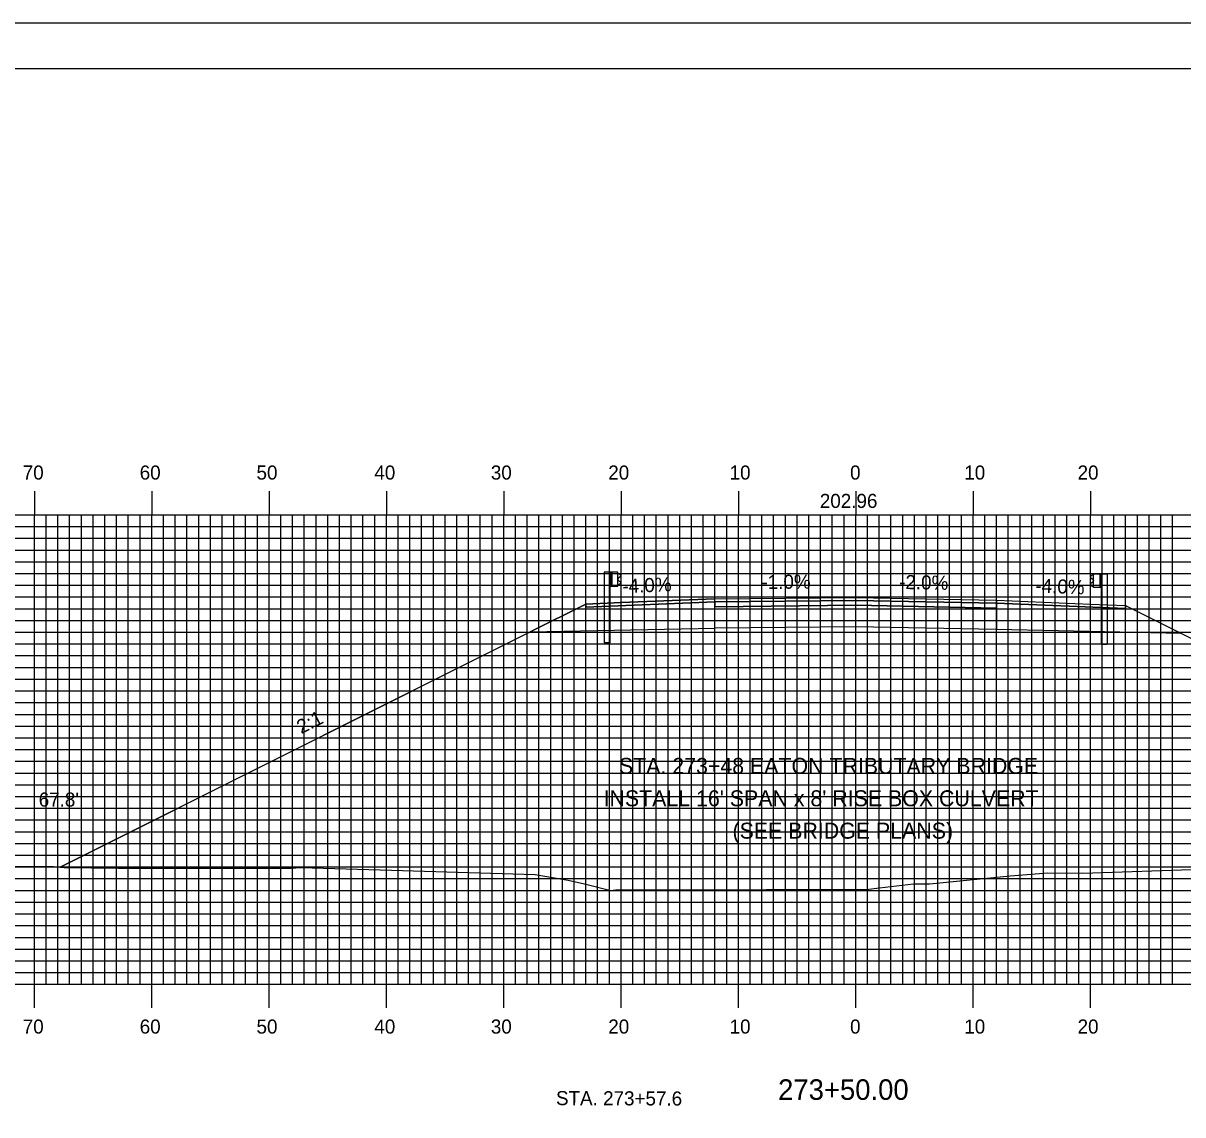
# Model space of a CAD drawing. Extents: x 1809013 to 1809356, y 442591 to 442811.
# Drawn here: x 1809107.4 to 1809206.2, y 442717.5 to 442810.5 of the extents above; entities that cross this region are included whole.
import ezdxf

# ---------------------------------------------------------------- set-up
doc = ezdxf.new("R2010")
doc.units = 0
for name, color, linetype in [('ANNOTATION', 7, 'Continuous'), ('BORDER', 7, 'Continuous'), ('BORING - NO REFUSAL', 7, 'Continuous'), ('D_Guardrail_Beam_Lt', 7, 'Continuous'), ('D_Guardrail_Beam_Rt', 7, 'Continuous'), ('D_Roadway_Centerline', 7, 'Continuous'), ('D_Roadway_Centerline_Text', 7, 'Continuous'), ('D_Roadway_Edge_Shoulder', 7, 'Continuous'), ('D_Roadway_Edge_TW', 7, 'Continuous'), ('D_Roadway_Pavement', 7, 'Continuous'), ('D_Roadway_SlopeLines', 7, 'Continuous'), ('D_Roadway_SubGrade', 7, 'Continuous'), ('D_Text_Standard', 7, 'Continuous'), ('H_V ANNOTATION', 7, 'Continuous'), ('MAJOR', 7, 'Continuous'), ('MINOR', 7, 'Continuous'), ('PLOT BOUNDARY', 7, 'Continuous'), ('S_Roadway_Centerline', 7, 'Continuous')]:
    doc.layers.add(name, color=color, linetype=linetype)

msp = doc.modelspace()

# ---------------------------------------------------------------- linework, layer by layer
at = {"layer": 'BORDER'}
msp.add_lwpolyline([(1809028.724, 442596.665), (1809348.724, 442596.665), (1809348.724, 442806.665), (1809028.724, 442806.665)], close=True, dxfattribs=at)
at = {"layer": 'D_Guardrail_Beam_Lt'}
for p, q in [((1809156.895, 442763.763), (1809156.895, 442757.763)), ((1809157.366, 442763.763), (1809156.895, 442763.763)), ((1809158.053, 442763.763), (1809157.366, 442763.763)), ((1809157.366, 442763.763), (1809157.366, 442762.596)), ((1809157.428, 442763.763), (1809157.428, 442762.596)), ((1809157.533, 442763.763), (1809157.533, 442762.596)), ((1809158.053, 442762.596), (1809158.053, 442763.763)), ((1809158.053, 442763.679), (1809158.128, 442763.665)), ((1809158.143, 442763.658), (1809158.287, 442763.558)), ((1809157.366, 442762.596), (1809158.053, 442762.596)), ((1809157.387, 442757.763), (1809157.387, 442762.596)), ((1809158.128, 442762.694), (1809158.053, 442762.679)), ((1809158.058, 442763.214), (1809158.058, 442763.144)), ((1809158.287, 442763.415), (1809158.091, 442763.279)), ((1809158.091, 442763.08), (1809158.287, 442762.944)), ((1809158.287, 442762.801), (1809158.143, 442762.701)), ((1809157.387, 442757.763), (1809156.895, 442757.763))]:
    msp.add_line(p, q, dxfattribs=at)
for centre, major_axis, start_param, end_param in [((1809158.119, 442763.624), (0.0417, 0), 0.959931, 1.376053), ((1809158.236, 442763.486), (0.0877, 0), 5.323254, 7.243116), ((1809158.137, 442763.214), (-0.0789, 0), 5.323254, 6.283185), ((1809158.137, 442763.144), (-0.0789, 0), 6.283185, 7.243116), ((1809158.119, 442762.735), (0.0417, 0), 4.907132, 5.323254), ((1809158.236, 442762.872), (0.0877, 0), 5.323254, 7.243116)]:
    msp.add_ellipse(centre, major_axis=major_axis, ratio=0.995501, start_param=start_param, end_param=end_param, dxfattribs=at)
at = {"layer": 'D_Guardrail_Beam_Rt'}
for p, q in [((1809198.505, 442763.539), (1809198.362, 442763.439)), ((1809198.595, 442763.56), (1809198.521, 442763.546)), ((1809198.595, 442763.644), (1809199.283, 442763.644)), ((1809198.595, 442762.477), (1809198.595, 442763.644)), ((1809199.116, 442763.644), (1809199.116, 442762.477)), ((1809199.22, 442763.644), (1809199.22, 442762.477)), ((1809199.283, 442763.644), (1809199.753, 442763.644)), ((1809199.283, 442763.644), (1809199.283, 442762.477)), ((1809199.753, 442763.644), (1809199.753, 442757.644)), ((1809198.362, 442763.296), (1809198.557, 442763.16)), ((1809198.557, 442762.961), (1809198.362, 442762.825)), ((1809198.362, 442762.681), (1809198.505, 442762.581)), ((1809198.521, 442762.575), (1809198.595, 442762.56)), ((1809198.591, 442763.095), (1809198.591, 442763.025)), ((1809199.283, 442762.477), (1809198.595, 442762.477)), ((1809199.262, 442757.644), (1809199.262, 442762.477)), ((1809199.262, 442757.644), (1809199.753, 442757.644))]:
    msp.add_line(p, q, dxfattribs=at)
for centre, major_axis, start_param, end_param in [((1809198.529, 442763.505), (-0.0417, 0), 4.907132, 5.323254), ((1809198.412, 442763.367), (-0.0877, 0), 5.323254, 7.243116), ((1809198.412, 442762.753), (-0.0877, 0), 5.323254, 7.243116), ((1809198.529, 442762.615), (-0.0417, 0), 0.959931, 1.376053), ((1809198.512, 442763.095), (0.0789, 0), 0, 0.959931), ((1809198.512, 442763.025), (0.0789, 0), 5.323254, 6.283185)]:
    msp.add_ellipse(centre, major_axis=major_axis, ratio=0.995501, start_param=start_param, end_param=end_param, dxfattribs=at)
at = {"layer": 'D_Roadway_Centerline'}
msp.add_lwpolyline([(1809110.506, 442738.65), (1809150.574, 442758.684), (1809155.324, 442761.059), (1809158.324, 442761.179), (1809166.324, 442761.499), (1809178.324, 442761.62), (1809190.324, 442761.38), (1809198.324, 442761.06), (1809201.324, 442760.94), (1809206.074, 442758.565), (1809246.409, 442738.398)], dxfattribs=at)
at = {"layer": 'D_Roadway_Edge_Shoulder'}
for points in [[(1809166.324, 442761.499), (1809158.324, 442761.179), (1809158.324, 442761.179), (1809155.324, 442761.059), (1809155.324, 442760.809), (1809166.324, 442761.249)], [(1809190.324, 442761.38), (1809198.324, 442761.06), (1809198.324, 442761.06), (1809201.324, 442760.94), (1809201.324, 442760.69), (1809190.324, 442761.13)]]:
    msp.add_lwpolyline(points, close=True, dxfattribs=at)
at = {"layer": 'D_Roadway_Edge_TW'}
msp.add_lwpolyline([(1809166.324, 442761.249), (1809166.324, 442761.499), (1809178.324, 442761.62), (1809190.324, 442761.38), (1809190.324, 442761.13), (1809178.324, 442761.37)], close=True, dxfattribs=at)
at = {"layer": 'D_Roadway_Pavement'}
msp.add_lwpolyline([(1809166.324, 442760.833), (1809166.324, 442761.249), (1809178.324, 442761.37), (1809190.324, 442761.13), (1809190.324, 442760.714), (1809178.324, 442760.954)], close=True, dxfattribs=at)
for points in [[(1809166.324, 442761.249), (1809166.324, 442760.833)], [(1809190.324, 442761.13), (1809190.324, 442760.714)]]:
    msp.add_lwpolyline(points, dxfattribs=at)
at = {"layer": 'D_Roadway_SlopeLines'}
for points in [[(1809155.324, 442761.059), (1809110.506, 442738.65)], [(1809201.324, 442760.94), (1809246.409, 442738.398)]]:
    msp.add_lwpolyline(points, dxfattribs=at)
at = {"layer": 'D_Roadway_SubGrade'}
for points in [[(1809166.324, 442760.833), (1809166.324, 442761.249), (1809155.324, 442760.809), (1809155.324, 442761.059), (1809150.574, 442758.684), (1809166.324, 442758.999)], [(1809166.324, 442758.999), (1809166.324, 442761.249), (1809166.324, 442760.833), (1809178.324, 442760.954), (1809190.324, 442760.714), (1809190.324, 442761.13), (1809190.324, 442758.88), (1809178.324, 442759.12)], [(1809190.324, 442760.714), (1809190.324, 442761.13), (1809201.324, 442760.69), (1809201.324, 442760.94), (1809206.074, 442758.565), (1809190.324, 442758.88)]]:
    msp.add_lwpolyline(points, close=True, dxfattribs=at)
at = {"layer": 'MAJOR'}
for p, q in [((1809108.324, 442770.669), (1809108.324, 442768.665)), ((1809118.324, 442770.669), (1809118.324, 442768.665)), ((1809128.324, 442770.669), (1809128.324, 442768.665)), ((1809138.324, 442770.669), (1809138.324, 442768.665)), ((1809148.324, 442770.669), (1809148.324, 442768.665)), ((1809158.324, 442770.669), (1809158.324, 442768.665)), ((1809168.324, 442770.669), (1809168.324, 442768.665)), ((1809178.324, 442770.669), (1809178.324, 442768.665)), ((1809188.324, 442770.669), (1809188.324, 442768.665)), ((1809198.324, 442770.669), (1809198.324, 442768.665)), ((1809038.324, 442768.665), (1809318.324, 442768.665)), ((1809038.324, 442768.665), (1809318.324, 442768.665)), ((1809108.324, 442728.665), (1809108.324, 442768.665)), ((1809118.324, 442728.665), (1809118.324, 442768.665)), ((1809128.324, 442728.665), (1809128.324, 442768.665)), ((1809138.324, 442728.665), (1809138.324, 442768.665)), ((1809148.324, 442728.665), (1809148.324, 442768.665)), ((1809158.324, 442728.665), (1809158.324, 442768.665)), ((1809168.324, 442728.665), (1809168.324, 442768.665)), ((1809178.324, 442728.665), (1809178.324, 442768.665)), ((1809188.324, 442728.665), (1809188.324, 442768.665)), ((1809198.324, 442728.665), (1809198.324, 442768.665)), ((1809038.324, 442763.665), (1809318.324, 442763.665)), ((1809038.324, 442758.665), (1809318.324, 442758.665)), ((1809038.324, 442753.665), (1809318.324, 442753.665)), ((1809038.324, 442748.665), (1809318.324, 442748.665)), ((1809038.324, 442743.665), (1809318.324, 442743.665)), ((1809038.324, 442738.665), (1809318.324, 442738.665)), ((1809038.324, 442733.665), (1809318.324, 442733.665)), ((1809038.324, 442728.665), (1809318.324, 442728.665)), ((1809038.324, 442728.665), (1809318.324, 442728.665)), ((1809108.324, 442726.661), (1809108.324, 442728.665)), ((1809118.324, 442726.661), (1809118.324, 442728.665)), ((1809128.324, 442726.661), (1809128.324, 442728.665)), ((1809138.324, 442726.661), (1809138.324, 442728.665)), ((1809148.324, 442726.661), (1809148.324, 442728.665)), ((1809158.324, 442726.661), (1809158.324, 442728.665)), ((1809168.324, 442726.661), (1809168.324, 442728.665)), ((1809178.324, 442726.661), (1809178.324, 442728.665)), ((1809188.324, 442726.661), (1809188.324, 442728.665)), ((1809198.324, 442726.661), (1809198.324, 442728.665))]:
    msp.add_line(p, q, dxfattribs=at)
at = {"layer": 'MINOR'}
for p, q in [((1809109.324, 442728.665), (1809109.324, 442768.665)), ((1809110.324, 442728.665), (1809110.324, 442768.665)), ((1809111.324, 442728.665), (1809111.324, 442768.665)), ((1809112.324, 442728.665), (1809112.324, 442768.665)), ((1809113.324, 442728.665), (1809113.324, 442768.665)), ((1809114.324, 442728.665), (1809114.324, 442768.665)), ((1809115.324, 442728.665), (1809115.324, 442768.665)), ((1809116.324, 442728.665), (1809116.324, 442768.665)), ((1809117.324, 442728.665), (1809117.324, 442768.665)), ((1809119.324, 442728.665), (1809119.324, 442768.665)), ((1809120.324, 442728.665), (1809120.324, 442768.665)), ((1809121.324, 442728.665), (1809121.324, 442768.665)), ((1809122.324, 442728.665), (1809122.324, 442768.665)), ((1809123.324, 442728.665), (1809123.324, 442768.665)), ((1809124.324, 442728.665), (1809124.324, 442768.665)), ((1809125.324, 442728.665), (1809125.324, 442768.665)), ((1809126.324, 442728.665), (1809126.324, 442768.665)), ((1809127.324, 442728.665), (1809127.324, 442768.665)), ((1809129.324, 442728.665), (1809129.324, 442768.665)), ((1809130.324, 442728.665), (1809130.324, 442768.665)), ((1809131.324, 442728.665), (1809131.324, 442768.665)), ((1809132.324, 442728.665), (1809132.324, 442768.665)), ((1809133.324, 442728.665), (1809133.324, 442768.665)), ((1809134.324, 442728.665), (1809134.324, 442768.665)), ((1809135.324, 442728.665), (1809135.324, 442768.665)), ((1809136.324, 442728.665), (1809136.324, 442768.665)), ((1809137.324, 442728.665), (1809137.324, 442768.665)), ((1809139.324, 442728.665), (1809139.324, 442768.665)), ((1809140.324, 442728.665), (1809140.324, 442768.665)), ((1809141.324, 442728.665), (1809141.324, 442768.665)), ((1809142.324, 442728.665), (1809142.324, 442768.665)), ((1809143.324, 442728.665), (1809143.324, 442768.665)), ((1809144.324, 442728.665), (1809144.324, 442768.665)), ((1809145.324, 442728.665), (1809145.324, 442768.665)), ((1809146.324, 442728.665), (1809146.324, 442768.665)), ((1809147.324, 442728.665), (1809147.324, 442768.665)), ((1809149.324, 442728.665), (1809149.324, 442768.665)), ((1809150.324, 442728.665), (1809150.324, 442768.665)), ((1809151.324, 442728.665), (1809151.324, 442768.665)), ((1809152.324, 442728.665), (1809152.324, 442768.665)), ((1809153.324, 442728.665), (1809153.324, 442768.665)), ((1809154.324, 442728.665), (1809154.324, 442768.665)), ((1809155.324, 442728.665), (1809155.324, 442768.665)), ((1809156.324, 442728.665), (1809156.324, 442768.665)), ((1809157.324, 442728.665), (1809157.324, 442768.665)), ((1809159.324, 442728.665), (1809159.324, 442768.665)), ((1809160.324, 442728.665), (1809160.324, 442768.665)), ((1809161.324, 442728.665), (1809161.324, 442768.665)), ((1809162.324, 442728.665), (1809162.324, 442768.665)), ((1809163.324, 442728.665), (1809163.324, 442768.665)), ((1809164.324, 442728.665), (1809164.324, 442768.665)), ((1809165.324, 442728.665), (1809165.324, 442768.665)), ((1809166.324, 442728.665), (1809166.324, 442768.665)), ((1809167.324, 442728.665), (1809167.324, 442768.665)), ((1809169.324, 442728.665), (1809169.324, 442768.665)), ((1809170.324, 442728.665), (1809170.324, 442768.665)), ((1809171.324, 442728.665), (1809171.324, 442768.665)), ((1809172.324, 442728.665), (1809172.324, 442768.665)), ((1809173.324, 442728.665), (1809173.324, 442768.665)), ((1809174.324, 442728.665), (1809174.324, 442768.665)), ((1809175.324, 442728.665), (1809175.324, 442768.665)), ((1809176.324, 442728.665), (1809176.324, 442768.665)), ((1809177.324, 442728.665), (1809177.324, 442768.665)), ((1809179.324, 442728.665), (1809179.324, 442768.665)), ((1809180.324, 442728.665), (1809180.324, 442768.665)), ((1809181.324, 442728.665), (1809181.324, 442768.665)), ((1809182.324, 442728.665), (1809182.324, 442768.665)), ((1809183.324, 442728.665), (1809183.324, 442768.665)), ((1809184.324, 442728.665), (1809184.324, 442768.665)), ((1809185.324, 442728.665), (1809185.324, 442768.665)), ((1809186.324, 442728.665), (1809186.324, 442768.665)), ((1809187.324, 442728.665), (1809187.324, 442768.665)), ((1809189.324, 442728.665), (1809189.324, 442768.665)), ((1809190.324, 442728.665), (1809190.324, 442768.665)), ((1809191.324, 442728.665), (1809191.324, 442768.665)), ((1809192.324, 442728.665), (1809192.324, 442768.665)), ((1809193.324, 442728.665), (1809193.324, 442768.665)), ((1809194.324, 442728.665), (1809194.324, 442768.665)), ((1809195.324, 442728.665), (1809195.324, 442768.665)), ((1809196.324, 442728.665), (1809196.324, 442768.665)), ((1809197.324, 442728.665), (1809197.324, 442768.665)), ((1809199.324, 442728.665), (1809199.324, 442768.665)), ((1809200.324, 442728.665), (1809200.324, 442768.665)), ((1809201.324, 442728.665), (1809201.324, 442768.665)), ((1809202.324, 442728.665), (1809202.324, 442768.665)), ((1809203.324, 442728.665), (1809203.324, 442768.665)), ((1809204.324, 442728.665), (1809204.324, 442768.665)), ((1809205.324, 442728.665), (1809205.324, 442768.665)), ((1809038.324, 442767.665), (1809318.324, 442767.665)), ((1809038.324, 442766.665), (1809318.324, 442766.665)), ((1809038.324, 442765.665), (1809318.324, 442765.665)), ((1809038.324, 442764.665), (1809318.324, 442764.665)), ((1809038.324, 442762.665), (1809318.324, 442762.665)), ((1809038.324, 442761.665), (1809318.324, 442761.665)), ((1809038.324, 442760.665), (1809318.324, 442760.665)), ((1809038.324, 442759.665), (1809318.324, 442759.665)), ((1809038.324, 442757.665), (1809318.324, 442757.665)), ((1809038.324, 442756.665), (1809318.324, 442756.665)), ((1809038.324, 442755.665), (1809318.324, 442755.665)), ((1809038.324, 442754.665), (1809318.324, 442754.665)), ((1809038.324, 442752.665), (1809318.324, 442752.665)), ((1809038.324, 442751.665), (1809318.324, 442751.665)), ((1809038.324, 442750.665), (1809318.324, 442750.665)), ((1809038.324, 442749.665), (1809318.324, 442749.665)), ((1809038.324, 442747.665), (1809318.324, 442747.665)), ((1809038.324, 442746.665), (1809318.324, 442746.665)), ((1809038.324, 442745.665), (1809318.324, 442745.665)), ((1809038.324, 442744.665), (1809318.324, 442744.665)), ((1809038.324, 442742.665), (1809318.324, 442742.665)), ((1809038.324, 442741.665), (1809318.324, 442741.665)), ((1809038.324, 442740.665), (1809318.324, 442740.665)), ((1809038.324, 442739.665), (1809318.324, 442739.665)), ((1809038.324, 442737.665), (1809318.324, 442737.665)), ((1809038.324, 442736.665), (1809318.324, 442736.665)), ((1809038.324, 442735.665), (1809318.324, 442735.665)), ((1809038.324, 442734.665), (1809318.324, 442734.665)), ((1809038.324, 442732.665), (1809318.324, 442732.665)), ((1809038.324, 442731.665), (1809318.324, 442731.665)), ((1809038.324, 442730.665), (1809318.324, 442730.665)), ((1809038.324, 442729.665), (1809318.324, 442729.665))]:
    msp.add_line(p, q, dxfattribs=at)
at = {"layer": 'PLOT BOUNDARY'}
msp.add_lwpolyline([(1809012.538, 442590.547), (1809352.538, 442590.547), (1809352.538, 442810.547), (1809012.538, 442810.547)], close=True, dxfattribs=at)
at = {"layer": 'S_Roadway_Centerline'}
msp.add_lwpolyline([(1809083.821, 442739.145), (1809107.986, 442738.706), (1809109.956, 442738.692), (1809110.869, 442738.623), (1809115.487, 442738.557), (1809130.201, 442738.555), (1809131.043, 442738.627), (1809138.768, 442738.398), (1809151.004, 442738.006), (1809153.805, 442737.544), (1809155.195, 442737.232), (1809157.333, 442736.691), (1809157.412, 442736.65), (1809157.869, 442736.716), (1809170.714, 442736.739), (1809179.222, 442736.752), (1809180.357, 442736.883), (1809183.239, 442737.215), (1809184.632, 442737.22), (1809191.496, 442737.908), (1809194.703, 442738.166), (1809197.67, 442738.136), (1809207.771, 442738.478)], dxfattribs=at)

# ---------------------------------------------------------------- texts
at = {"layer": 'ANNOTATION'}
for s, rotation, p in [('-1.0%', 0.57743, (1809170.293, 442762.339)), ('-2.0%', 358.85424, (1809182.01, 442762.347)), ('-4.0%', 2.29061, (1809158.456, 442761.986)), ('-4.0%', 357.70939, (1809193.616, 442762.05)), ('2:1', 26.56505, (1809131.06, 442749.963))]:
    msp.add_text(s, height=1.2, rotation=rotation, dxfattribs=at).set_placement(p)
for s, p in [('STA. 273+48 EATON TRIBUTARY BRIDGE', (1809158.141, 442746.593)), ("INSTALL 16' SPAN x 8' RISE BOX CULVERT", (1809156.831, 442743.833)), ('(SEE BRIDGE PLANS)', (1809167.82, 442741.073))]:
    msp.add_text(s, height=1.36, dxfattribs=at).set_placement(p)
at = {"layer": 'BORING - NO REFUSAL'}
msp.add_text('STA. 273+57.6', height=1.2, rotation=359.81416, dxfattribs=at).set_placement((1809152.776, 442718.37))
at = {"layer": 'D_Roadway_Centerline'}
for s, p in [('C', (1809178.319, 442761.62)), ('L', (1809178.324, 442761.613))]:
    msp.add_text(s, height=0.0146, dxfattribs=at).set_placement(p)
at = {"layer": 'D_Roadway_Centerline_Text'}
msp.add_text('202.96', height=1.2, dxfattribs=at).set_placement((1809175.263, 442769.248))
at = {"layer": 'D_Text_Standard'}
msp.add_text("67.8'", height=1.2, dxfattribs=at).set_placement((1809108.69, 442743.804))
at = {"layer": 'H_V ANNOTATION'}
for s, height, p in [('70', 1.2, (1809107.328, 442771.665)), ('60', 1.2, (1809117.297, 442771.665)), ('50', 1.2, (1809127.254, 442771.665)), ('40', 1.2, (1809137.297, 442771.665)), ('30', 1.2, (1809147.222, 442771.665)), ('20', 1.2, (1809157.232, 442771.665)), ('10', 1.2, (1809167.575, 442771.665)), ('0', 1.2, (1809177.842, 442771.665)), ('10', 1.2, (1809187.575, 442771.665)), ('20', 1.2, (1809197.232, 442771.665)), ('70', 1.2, (1809107.328, 442724.465)), ('60', 1.2, (1809117.297, 442724.465)), ('50', 1.2, (1809127.254, 442724.465)), ('40', 1.2, (1809137.297, 442724.465)), ('30', 1.2, (1809147.222, 442724.465)), ('20', 1.2, (1809157.232, 442724.465)), ('10', 1.2, (1809167.575, 442724.465)), ('0', 1.2, (1809177.842, 442724.465)), ('10', 1.2, (1809187.575, 442724.465)), ('20', 1.2, (1809197.232, 442724.465)), ('273+50.00', 1.75, (1809171.707, 442718.821))]:
    msp.add_text(s, height=height, dxfattribs=at).set_placement(p)

doc.saveas('drawing.dxf')
